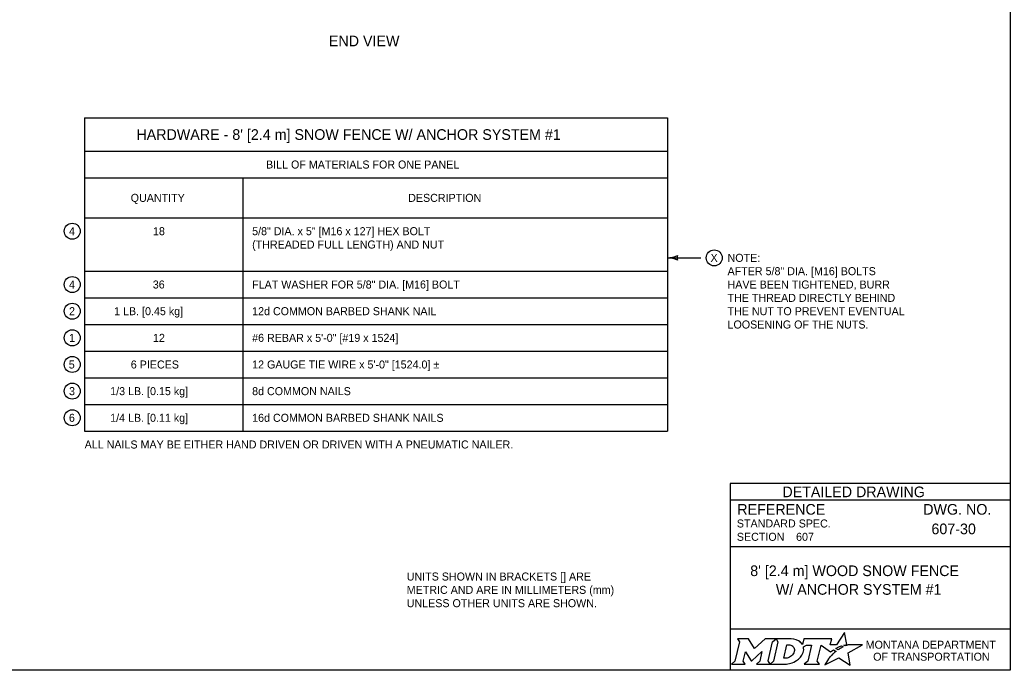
# Model space of a CAD drawing. Extents: x 49991 to 79985, y 47703 to 60542.
# Drawn here: x 50009.32 to 50016.75, y 49987.8 to 49992.68 of the extents above; entities that cross this region are included whole.
import ezdxf

# ---------------------------------------------------------------- set-up
doc = ezdxf.new("R2010")
doc.units = 0
for name, color, linetype in [('Default', 7, 'Continuous'), ('Level 1', 7, 'Continuous'), ('Level 2', 7, 'Continuous'), ('Level 3', 7, 'Continuous'), ('Level 5', 7, 'Continuous')]:
    doc.layers.add(name, color=color, linetype=linetype)

msp = doc.modelspace()

# ---------------------------------------------------------------- linework, layer by layer
at = {"layer": 'Default'}
for points in [[(50014.7056, 49988.0338), (50014.7197, 49988.0104), (50014.6862, 49987.8671), (50014.6605, 49987.8446), (50014.7621, 49987.8446), (50014.7486, 49987.8674), (50014.7648, 49987.9375), (50014.8085, 49987.8685), (50014.8138, 49987.8685), (50014.8889, 49987.938), (50014.8725, 49987.8669), (50014.8478, 49987.8449), (50014.9494, 49987.8449), (50014.9356, 49987.8682), (50014.9688, 49988.0106)], [(50014.9688, 49988.0106), (50014.9941, 49988.0338), (50014.9117, 49988.0338), (50014.8321, 49987.9608), (50014.7876, 49988.0335), (50014.7056, 49988.0338)], [(50015.1077, 49988.0338), (50014.9941, 49988.0338), (50015.0088, 49988.0109), (50014.9749, 49987.8671), (50014.9494, 49987.8449), (50015.06, 49987.8449)], [(50015.5126, 49987.9811), (50015.5023, 49987.9867), (50015.5139, 49987.9895), (50015.5255, 49987.9915), (50015.5081, 49988.0816), (50015.4486, 49987.9903), (50015.4013, 49987.9896), (50015.4116, 49988.0337), (50015.2024, 49988.0338), (50015.1923, 49987.9913), (50015.1865, 49987.9996)], [(50015.1317, 49987.9471), (50015.1305, 49987.939), (50015.1273, 49987.9297), (50015.1231, 49987.9215), (50015.1175, 49987.914), (50015.111, 49987.9071), (50015.1031, 49987.9008), (50015.0948, 49987.8961), (50015.0857, 49987.8922), (50015.0766, 49987.8899), (50015.0674, 49987.889), (50015.0515, 49987.889), (50015.0751, 49987.989), (50015.0911, 49987.989), (50015.0987, 49987.9884), (50015.1063, 49987.9865), (50015.1129, 49987.9835), (50015.119, 49987.9793), (50015.1238, 49987.9743), (50015.1275, 49987.9683), (50015.1302, 49987.9621), (50015.1318, 49987.9547), (50015.1318, 49987.9517), (50015.1317, 49987.9471)], [(50015.1991, 49987.9747), (50015.2237, 49987.9878), (50015.2606, 49987.9878), (50015.232, 49987.8673), (50015.2045, 49987.8446), (50015.3207, 49987.8446), (50015.3037, 49987.8675), (50015.3319, 49987.9877), (50015.4032, 49987.936), (50015.4243, 49987.9511), (50015.444, 49987.9402)], [(50015.3882, 49987.8843), (50015.3729, 49987.8599), (50015.3682, 49987.8524), (50015.3624, 49987.8438), (50015.3601, 49987.8395), (50015.4654, 49987.8926), (50015.5493, 49987.8375), (50015.5362, 49987.9302), (50015.6431, 49987.9886), (50015.5938, 49987.9894), (50015.5637, 49987.9898), (50015.5429, 49987.9901), (50015.5361, 49987.9886), (50015.5312, 49987.9874), (50015.5228, 49987.9851), (50015.5126, 49987.9811)], [(50015.4622, 49987.9535), (50015.4598, 49987.9518), (50015.4415, 49987.9614), (50015.4518, 49987.9671), (50015.4559, 49987.9693), (50015.4645, 49987.9733), (50015.4702, 49987.9759), (50015.4781, 49987.9789), (50015.4854, 49987.9816), (50015.4972, 49987.9742), (50015.4932, 49987.9721), (50015.4886, 49987.9696), (50015.4844, 49987.9674), (50015.4794, 49987.9645), (50015.4775, 49987.9634), (50015.4748, 49987.9618), (50015.4723, 49987.9604), (50015.47, 49987.9588), (50015.4674, 49987.957), (50015.4647, 49987.9552), (50015.4622, 49987.9535)], [(50015.1057, 49987.8522), (50015.1141, 49987.8548), (50015.1271, 49987.8602), (50015.1475, 49987.8712)], [(50015.4021, 49987.9004), (50015.4021, 49987.9004)]]:
    msp.add_lwpolyline(points, dxfattribs=at)
for centre, radius, start, end in [((50015.1308, 49987.9554), 0.0709, 339.53292, 15.85821), ((50015.0868, 49987.9727), 0.1183, 300.91025, 339.13831)]:
    msp.add_arc(centre, radius, start, end, dxfattribs=at)
for centre, major_axis, ratio, start_param, end_param in [((50015.1056, 49987.9864), (0.0834, -0.0037), 0.568097, 0.61298, 1.570796), ((50015.1612, 49987.9937), (0.0361, -0.0295), 0.469099, 1.225588, 1.570796), ((50015.4329, 49987.9305), (-0.0112, -0.0097), 0.021651, 3.157348, 6.283185), ((50015.3952, 49987.8923), (-0.00694, -0.00806), 0.008222, 0, 3.137361), ((50015.4119, 49987.9106), (-0.0098, -0.0102), 0.016458, 3.141593, 6.279097), ((50015.0603, 49987.9932), (0, 0.1484), 0.987302, 3.139398, 3.456847)]:
    msp.add_ellipse(centre, major_axis=major_axis, ratio=ratio, start_param=start_param, end_param=end_param, dxfattribs=at)
at = {"layer": 'Level 1'}
msp.add_lwpolyline([(49999.3835, 49998.9992), (50016.7501, 49998.9992), (50016.7501, 49987.7988), (49999.3835, 49987.7988)], close=True, dxfattribs=at)
at = {"layer": 'Level 2'}
for p, q in [((50009.8095, 49991.942), (50009.8095, 49989.592)), ((50009.8095, 49991.942), (50014.1792, 49991.942)), ((50014.1792, 49991.942), (50014.1792, 49989.592)), ((50009.8095, 49991.692), (50014.1792, 49991.692)), ((50009.8095, 49991.492), (50014.1792, 49991.492)), ((50010.9955, 49991.492), (50010.9955, 49989.592)), ((50009.8095, 49991.192), (50014.1792, 49991.192)), ((50009.8095, 49990.792), (50014.1792, 49990.792)), ((50009.8095, 49990.592), (50014.1792, 49990.592)), ((50009.8095, 49990.392), (50014.1792, 49990.392)), ((50009.8095, 49990.192), (50014.1792, 49990.192)), ((50009.8095, 49989.992), (50014.1792, 49989.992)), ((50009.8095, 49989.792), (50014.1792, 49989.792)), ((50009.8095, 49989.592), (50014.1792, 49989.592))]:
    msp.add_line(p, q, dxfattribs=at)
for centre in [(50009.7164, 49991.092), (50014.5305, 49990.892), (50009.7164, 49990.692), (50009.7164, 49990.492), (50009.7164, 49990.292), (50009.7164, 49990.092), (50009.7164, 49989.892), (50009.7164, 49989.692)]:
    msp.add_circle(centre, 0.06, dxfattribs=at)
at = {"layer": 'Level 3'}
msp.add_line((50014.1792, 49990.892), (50014.4305, 49990.892), dxfattribs=at)
for centre, radius, start, end in [((50014.1677, 49991.1247), 0.233, 272.82731, 292.07716), ((50014.3074, 49990.892), 0.0548, 162.13882, 197.86118), ((50014.1701, 49990.6699), 0.2223, 67.45601, 87.63952)]:
    msp.add_arc(centre, radius, start, end, dxfattribs=at)
at = {"layer": 'Level 5'}
for p, q in [((50016.7501, 49989.1988), (50014.6501, 49989.1988)), ((50014.6501, 49989.1988), (50014.6501, 49987.7988)), ((50016.7501, 49989.0738), (50014.6501, 49989.0738)), ((50016.3862, 49988.8587), (50016.3862, 49988.8587)), ((50015.1444, 49988.7993), (50015.1444, 49988.7993)), ((50016.7501, 49988.7238), (50014.6501, 49988.7238)), ((50015.7001, 49988.4747), (50015.7001, 49988.4747)), ((50016.7501, 49988.1057), (50014.6501, 49988.1057))]:
    msp.add_line(p, q, dxfattribs=at)

# ---------------------------------------------------------------- texts
at = {"layer": 'Default'}
for s, p in [('MONTANA DEPARTMENT', (50015.6663, 49987.96)), ('OF TRANSPORTATION', (50015.7225, 49987.87))]:
    msp.add_text(s, height=0.06, dxfattribs=at).set_placement(p)
at = {"layer": 'Level 2'}
for s, height, p in [('END VIEW', 0.08, (50011.6413, 49992.479)), ("HARDWARE - 8' [2.4 m] SNOW FENCE W/ ANCHOR SYSTEM #1", 0.08, (50010.1976, 49991.777)), ('BILL OF MATERIALS FOR ONE PANEL', 0.06, (50011.1698, 49991.562)), ('QUANTITY', 0.06, (50010.155, 49991.312)), ('DESCRIPTION', 0.06, (50012.2355, 49991.312)), ('4', 0.06, (50009.6925, 49991.062)), ('18', 0.06, (50010.3221, 49991.062)), ('5/8" DIA. x 5" [M16 x 127] HEX BOLT', 0.06, (50011.0655, 49991.062)), ('(THREADED FULL LENGTH) AND NUT', 0.06, (50011.0655, 49990.962)), ('X', 0.06, (50014.503, 49990.862)), ('NOTE:', 0.06, (50014.6305, 49990.862)), ('AFTER 5/8" DIA. [M16] BOLTS', 0.06, (50014.6305, 49990.762)), ('4', 0.06, (50009.6925, 49990.662)), ('36', 0.06, (50010.3204, 49990.662)), ('FLAT WASHER FOR 5/8" DIA. [M16] BOLT', 0.06, (50011.0655, 49990.662)), ('HAVE BEEN TIGHTENED, BURR', 0.06, (50014.6305, 49990.662)), ('THE THREAD DIRECTLY BEHIND', 0.06, (50014.6305, 49990.562)), ('2', 0.06, (50009.6925, 49990.462)), ('1 LB. [0.45 kg]', 0.06, (50010.0305, 49990.462)), ('12d COMMON BARBED SHANK NAIL', 0.06, (50011.0655, 49990.462)), ('THE NUT TO PREVENT EVENTUAL', 0.06, (50014.6305, 49990.462)), ('LOOSENING OF THE NUTS.', 0.06, (50014.6305, 49990.362)), ('1', 0.06, (50009.6931, 49990.262)), ('12', 0.06, (50010.3221, 49990.262)), ('#6 REBAR x 5\'-0" [#19 x 1524]', 0.06, (50011.0655, 49990.262)), ('5', 0.06, (50009.6905, 49990.062)), ('6 PIECES', 0.06, (50010.1556, 49990.062)), ('12 GAUGE TIE WIRE x 5\'-0" [1524.0] ±', 0.06, (50011.0655, 49990.062)), ('3', 0.06, (50009.6925, 49989.862)), ('1/3 LB. [0.15 kg]', 0.06, (50010.0011, 49989.862)), ('8d COMMON NAILS            ', 0.06, (50011.0655, 49989.862)), ('6', 0.06, (50009.6917, 49989.662)), ('1/4 LB. [0.11 kg]', 0.06, (50010.0011, 49989.662)), ('16d COMMON BARBED SHANK NAILS', 0.06, (50011.0655, 49989.662)), ('ALL NAILS MAY BE EITHER HAND DRIVEN OR DRIVEN WITH A PNEUMATIC NAILER.', 0.06, (50009.8095, 49989.462)), ('607', 0.06, (50015.1444, 49988.7693)), ('607-30', 0.08, (50016.1596, 49988.8187)), ('UNITS SHOWN IN BRACKETS [] ARE ', 0.06, (50012.2247, 49988.4715)), ("8' [2.4 m] WOOD SNOW FENCE", 0.08, (50014.8006, 49988.5047)), ('METRIC AND ARE IN MILLIMETERS (mm) ', 0.06, (50012.2247, 49988.3715)), ('W/ ANCHOR SYSTEM #1', 0.08, (50014.9927, 49988.3647)), ('UNLESS OTHER UNITS ARE SHOWN.', 0.06, (50012.2247, 49988.2715))]:
    msp.add_text(s, height=height, dxfattribs=at).set_placement(p)
at = {"layer": 'Level 5'}
for s, height, p in [('DETAILED DRAWING', 0.0799, (50015.0418, 49989.0963)), ('REFERENCE', 0.08, (50014.7037, 49988.9654)), ('DWG. NO.', 0.08, (50016.0979, 49988.9654)), ('STANDARD SPEC.', 0.06, (50014.7004, 49988.8694)), ('SECTION', 0.06, (50014.7004, 49988.7694))]:
    msp.add_text(s, height=height, dxfattribs=at).set_placement(p)

doc.saveas('drawing.dxf')
